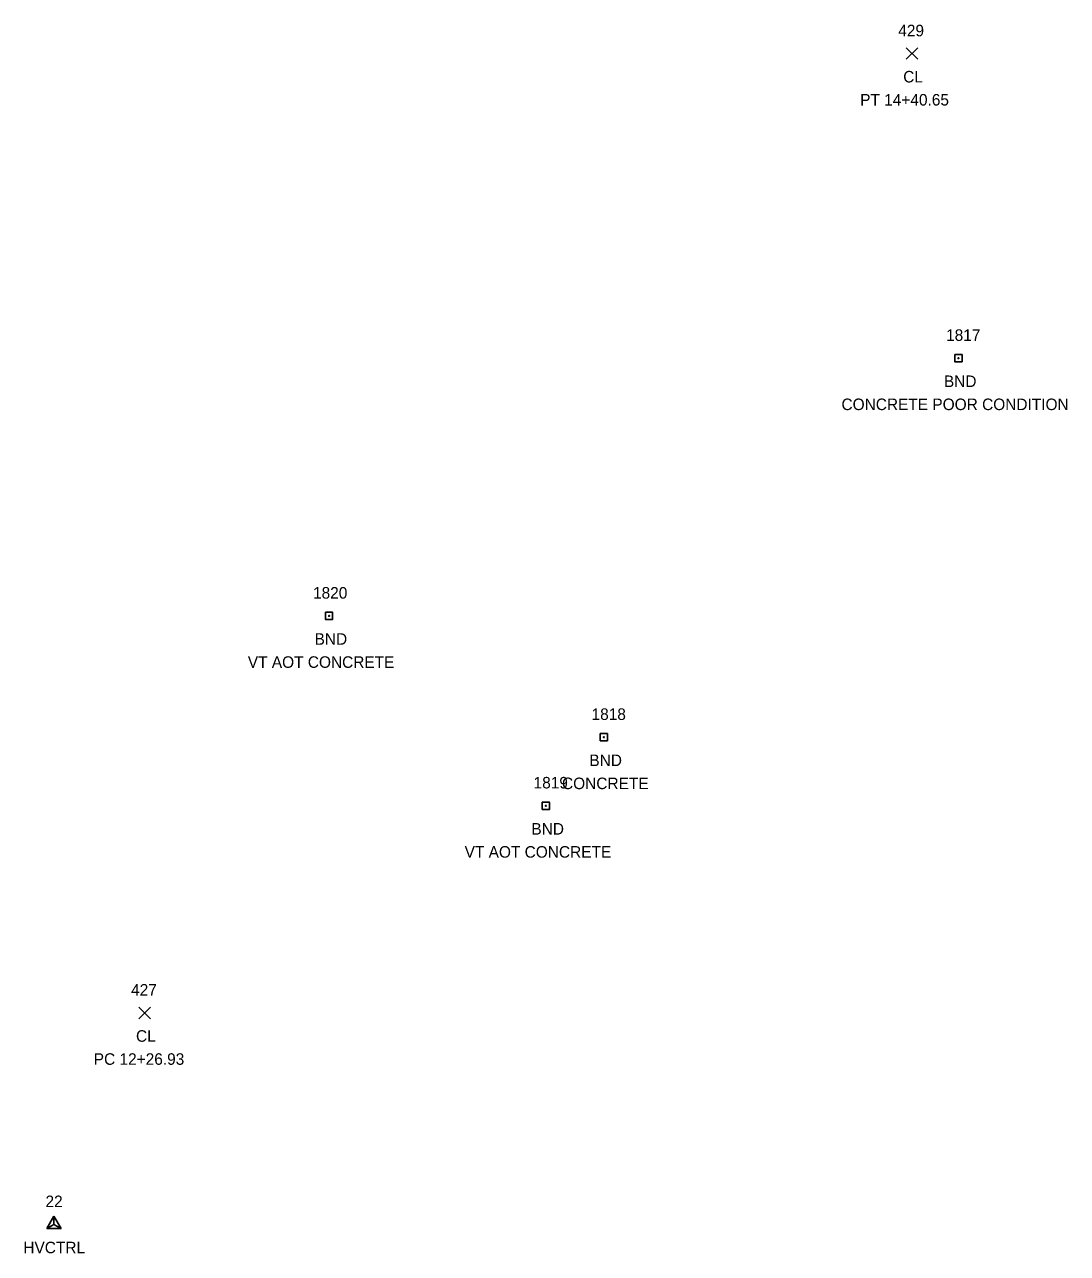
# Model space of a CAD drawing. Extents: x 1767353 to 1772625, y 740790 to 747702.
# Drawn here: x 1771505.8 to 1771686.6, y 746771.8 to 746984.9 of the extents above; entities that cross this region are included whole.
import ezdxf

# ---------------------------------------------------------------- set-up
doc = ezdxf.new("R2010")
doc.units = 0
for name, color, linetype in [('A_A', 7, 'Continuous'), ('A_C', 7, 'Continuous'), ('A_I', 7, 'Continuous'), ('A_TIC', 7, 'Continuous'), ('C_A', 7, 'Continuous'), ('C_I', 7, 'Continuous'), ('CPSM', 7, 'Continuous'), ('Level 18', 7, 'Continuous'), ('M_A', 7, 'Continuous'), ('M_C', 7, 'Continuous'), ('M_I', 7, 'Continuous')]:
    doc.layers.add(name, color=color, linetype=linetype)

msp = doc.modelspace()

# ---------------------------------------------------------------- linework, layer by layer
at = {"layer": 'A_TIC'}
for points in [[(1771658.62, 746978.85), (1771660.62, 746980.84)], [(1771660.62, 746978.85), (1771658.62, 746980.84)], [(1771525.64, 746812.54), (1771527.64, 746814.54)], [(1771527.64, 746812.54), (1771525.64, 746814.54)]]:
    msp.add_lwpolyline(points, dxfattribs=at)
at = {"layer": 'CPSM'}
for p, q in [((1771509.65, 746776.15), (1771510.9, 746778.32)), ((1771509.65, 746776.15), (1771510.9, 746778.32)), ((1771509.65, 746776.15), (1771510.9, 746778.32)), ((1771509.65, 746776.15), (1771510.9, 746778.32)), ((1771509.65, 746776.15), (1771510.9, 746776.87)), ((1771509.65, 746776.15), (1771510.9, 746776.87)), ((1771509.65, 746776.15), (1771510.9, 746776.87)), ((1771509.65, 746776.15), (1771510.9, 746776.87)), ((1771512.15, 746776.15), (1771510.9, 746778.32)), ((1771510.9, 746776.87), (1771510.9, 746778.32)), ((1771512.15, 746776.15), (1771510.9, 746778.32)), ((1771510.9, 746776.87), (1771510.9, 746778.32)), ((1771512.15, 746776.15), (1771510.9, 746778.32)), ((1771510.9, 746776.87), (1771510.9, 746778.32)), ((1771512.15, 746776.15), (1771510.9, 746778.32)), ((1771510.9, 746776.87), (1771510.9, 746778.32)), ((1771510.9, 746776.87), (1771510.9, 746776.87)), ((1771510.9, 746776.87), (1771512.15, 746776.15)), ((1771510.9, 746776.87), (1771510.9, 746776.87)), ((1771510.9, 746776.87), (1771512.15, 746776.15)), ((1771510.9, 746776.87), (1771510.9, 746776.87)), ((1771510.9, 746776.87), (1771512.15, 746776.15)), ((1771510.9, 746776.87), (1771510.9, 746776.87)), ((1771510.9, 746776.87), (1771512.15, 746776.15)), ((1771509.65, 746776.15), (1771512.15, 746776.15)), ((1771509.65, 746776.15), (1771512.15, 746776.15)), ((1771509.65, 746776.15), (1771512.15, 746776.15)), ((1771509.65, 746776.15), (1771512.15, 746776.15))]:
    msp.add_line(p, q, dxfattribs=at)
at = {"layer": 'Level 18'}
for points in [[(1771667.05, 746927.66), (1771668.3, 746927.66), (1771668.3, 746926.41), (1771667.05, 746926.41)], [(1771557.96, 746882.99), (1771559.21, 746882.99), (1771559.21, 746881.74), (1771557.96, 746881.74)], [(1771605.59, 746861.96), (1771606.84, 746861.96), (1771606.84, 746860.71), (1771605.59, 746860.71)], [(1771595.55, 746850.07), (1771596.8, 746850.07), (1771596.8, 746848.82), (1771595.55, 746848.82)]]:
    msp.add_lwpolyline(points, close=True, dxfattribs=at)
for centre in [(1771667.67, 746927.04), (1771558.59, 746882.36), (1771606.22, 746861.33), (1771596.17, 746849.45)]:
    msp.add_circle(centre, 0.0833, dxfattribs=at)

# ---------------------------------------------------------------- texts
at = {"layer": 'A_A'}
for p in [(1771658.11, 746974.84), (1771525.13, 746808.54)]:
    msp.add_text('CL', height=2, dxfattribs=at).set_placement(p)
at = {"layer": 'A_C'}
for s, p in [('PT 14+40.65', (1771650.65, 746970.84)), ('PC 12+26.93', (1771517.81, 746804.54))]:
    msp.add_text(s, height=2, dxfattribs=at).set_placement(p)
at = {"layer": 'A_I'}
for s, p in [('429', (1771657.25, 746982.84)), ('427', (1771524.28, 746816.54))]:
    msp.add_text(s, height=2, dxfattribs=at).set_placement(p)
at = {"layer": 'C_A'}
msp.add_text('HVCTRL', height=2, dxfattribs=at).set_placement((1771505.6, 746771.87))
msp.add_text('HVCTRL', height=2, dxfattribs=at).set_placement((1771505.6, 746771.87))
msp.add_text('HVCTRL', height=2, dxfattribs=at).set_placement((1771505.6, 746771.87))
msp.add_text('HVCTRL', height=2, dxfattribs=at).set_placement((1771505.6, 746771.87))
at = {"layer": 'C_I'}
msp.add_text('22', height=2, dxfattribs=at).set_placement((1771509.44, 746779.87))
msp.add_text('22', height=2, dxfattribs=at).set_placement((1771509.44, 746779.87))
msp.add_text('22', height=2, dxfattribs=at).set_placement((1771509.44, 746779.87))
msp.add_text('22', height=2, dxfattribs=at).set_placement((1771509.44, 746779.87))
at = {"layer": 'M_A'}
for p in [(1771665.16, 746922.04), (1771556.08, 746877.36), (1771603.71, 746856.33), (1771593.66, 746844.45)]:
    msp.add_text('BND', height=2, dxfattribs=at).set_placement(p)
at = {"layer": 'M_C'}
for s, p in [('CONCRETE POOR CONDITION', (1771647.41, 746918.04)), ('VT AOT CONCRETE', (1771544.51, 746873.36)), ('CONCRETE', (1771598.97, 746852.33)), ('VT AOT CONCRETE', (1771582.09, 746840.45))]:
    msp.add_text(s, height=2, dxfattribs=at).set_placement(p)
at = {"layer": 'M_I'}
for s, p in [('1817', (1771665.54, 746930.04)), ('1820', (1771555.81, 746885.36)), ('1818', (1771604.09, 746864.33)), ('1819', (1771594.04, 746852.45))]:
    msp.add_text(s, height=2, dxfattribs=at).set_placement(p)

doc.saveas('drawing.dxf')
